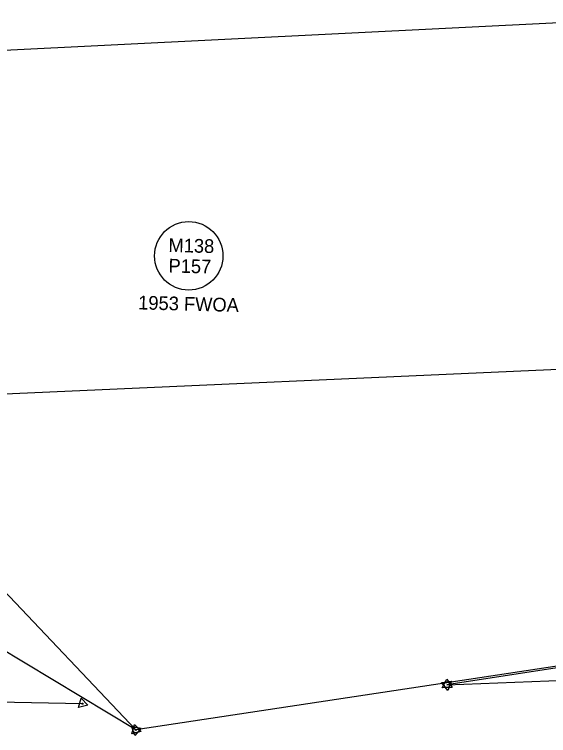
# Model space of a CAD drawing. Extents: x 325018 to 414989, y 1517547 to 1550415.
# Drawn here: x 359543.3 to 359748.2, y 1524601.5 to 1524878 of the extents above; entities that cross this region are included whole.
import ezdxf

# ---------------------------------------------------------------- set-up
doc = ezdxf.new("R2010")
doc.units = 0
for name, color, linetype in [('Level 56', 7, 'Continuous'), ('MEE', 7, 'Continuous'), ('MHBWOA', 7, 'Continuous'), ('MJT', 7, 'Continuous'), ('MRBL2', 7, 'Continuous')]:
    doc.layers.add(name, color=color, linetype=linetype)

msp = doc.modelspace()

# ---------------------------------------------------------------- linework, layer by layer
at = {"layer": 'Level 56'}
msp.add_circle((359610.16, 1524785.4), 13.12, dxfattribs=at)
at = {"layer": 'MEE'}
msp.add_line((359569.39, 1524613.71), (359304.19, 1524618.57), dxfattribs=at)
for points in [[(359567.82, 1524612.2), (359568.87, 1524615.83)], [(359568.87, 1524615.83), (359571.48, 1524613.1)], [(359571.48, 1524613.1), (359567.82, 1524612.2)]]:
    msp.add_lwpolyline(points, dxfattribs=at)
msp.add_circle((359569.39, 1524613.71), 0.227, dxfattribs=at)
at = {"layer": 'MHBWOA'}
for p, q in [((359185.58, 1524846.77), (359814.81, 1524877.96)), ((359589.86, 1524603.62), (359185.58, 1524846.77)), ((359805.62, 1524636.3), (359589.86, 1524603.62)), ((359802.12, 1524635.25), (359709.21, 1524620.97)), ((359709.21, 1524620.97), (360017.1, 1524633.08))]:
    msp.add_line(p, q, dxfattribs=at)
for points in [[(359707.17, 1524621.77), (359710.91, 1524622.34)], [(359709.54, 1524618.82), (359707.17, 1524621.77)], [(359707.36, 1524619.81), (359709.12, 1524623.15)], [(359709.12, 1524623.15), (359711.14, 1524619.96)], [(359710.91, 1524622.34), (359709.54, 1524618.82)], [(359711.14, 1524619.96), (359707.36, 1524619.81)], [(359589.44, 1524601.48), (359588.22, 1524605.06)], [(359588.22, 1524605.06), (359591.93, 1524604.32)], [(359591.93, 1524604.32), (359589.44, 1524601.48)]]:
    msp.add_lwpolyline(points, dxfattribs=at)
for centre, radius in [((359709.21, 1524620.97), 1.09), ((359709.2, 1524620.97), 1.09), ((359589.86, 1524603.62), 0.227)]:
    msp.add_circle(centre, radius, dxfattribs=at)
at = {"layer": 'MJT'}
msp.add_line((359589.86, 1524603.62), (359351.37, 1524854.99), dxfattribs=at)
for points in [[(359588.28, 1524602.12), (359589.36, 1524605.74)], [(359589.36, 1524605.74), (359591.96, 1524603)], [(359591.96, 1524603), (359588.28, 1524602.12)]]:
    msp.add_lwpolyline(points, dxfattribs=at)
msp.add_circle((359589.86, 1524603.62), 1.09, dxfattribs=at)
at = {"layer": 'MRBL2'}
msp.add_line((357680.4, 1524649.21), (360123.46, 1524758.65), dxfattribs=at)

# ---------------------------------------------------------------- texts
at = {"layer": 'Level 56'}
for s, p in [('M138', (359602.32, 1524786.91)), ('P157', (359602.34, 1524779.04)), ('1953 FWOA', (359590.71, 1524764.88))]:
    msp.add_text(s, height=5.249, rotation=358.5141, dxfattribs=at).set_placement(p)

doc.saveas('drawing.dxf')
